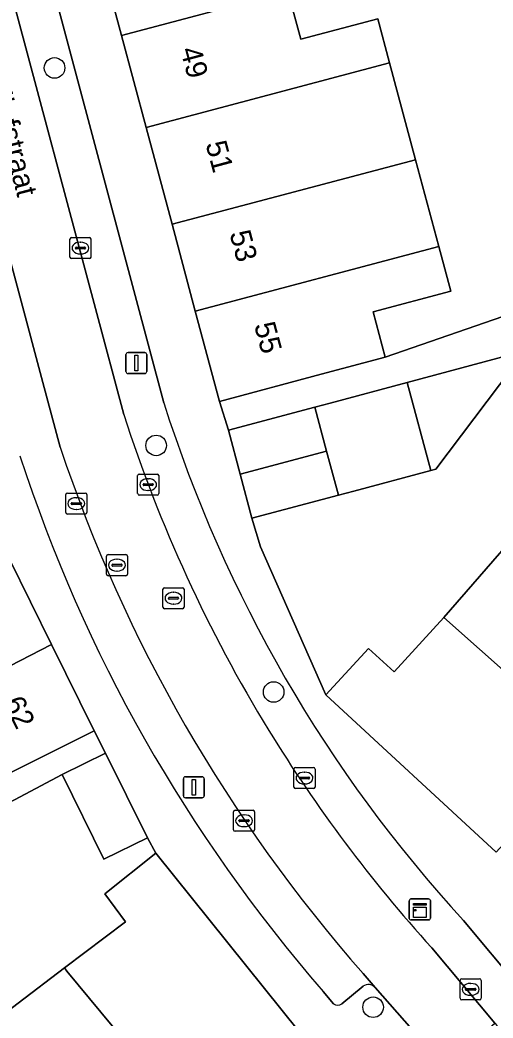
# Model space of a CAD drawing. Extents: x 162542 to 163147, y 380779 to 381521.
# Drawn here: x 163005.41 to 163027.86, y 380934.95 to 380982.36 of the extents above; entities that cross this region are included whole.
import ezdxf

# ---------------------------------------------------------------- set-up
doc = ezdxf.new("R2010")
doc.units = 0
for name, color, linetype in [('IMGEO_Boom', 7, 'Continuous'), ('IMGEO_Erf', 7, 'Continuous'), ('IMGEO_Kast', 7, 'Continuous'), ('IMGEO_Kolk', 7, 'Continuous'), ('IMGEO_Lichtmast', 7, 'Continuous'), ('IMGEO_Muur', 7, 'Continuous'), ('IMGEO_Openbare_ruimte_label', 7, 'Continuous'), ('IMGEO_Pand', 7, 'Continuous'), ('IMGEO_Pand_nummerreeks', 7, 'Continuous'), ('IMGEO_Parkeervlak_open', 7, 'Continuous'), ('IMGEO_Rijbaan_lokaal_open', 7, 'Continuous'), ('IMGEO_Rioolput', 7, 'Continuous'), ('IMGEO_Voetpad_open', 7, 'Continuous')]:
    doc.layers.add(name, color=color, linetype=linetype)

msp = doc.modelspace()

# ---------------------------------------------------------------- linework, layer by layer
at = {"layer": 'IMGEO_Boom'}
for centre in [(163007.052, 380980.083), (163011.873, 380962.151), (163017.451, 380950.44), (163022.172, 380935.467)]:
    msp.add_circle(centre, 0.489, dxfattribs=at)
at = {"layer": 'IMGEO_Erf'}
for points in [[(163018.128, 380983.725), (163018.739, 380981.442), (163022.394, 380982.42), (163022.954, 380980.325), (163024.185, 380975.725), (163025.287, 380971.603), (163025.853, 380969.486), (163022.173, 380968.502), (163022.75, 380966.347), (163029.615, 380968.727)], [(163029.387, 380966.638), (163025.146, 380961.029), (163024.914, 380960.967), (163021.252, 380959.987), (163020.522, 380959.792), (163016.421, 380958.694), (163016.826, 380957.343), (163019.935, 380950.306), (163021.945, 380952.504), (163023.178, 380951.397), (163025.524, 380953.976), (163028.918, 380957.88)], [(163003.112, 380933.989), (163007.525, 380937.333), (163010.415, 380939.523), (163009.443, 380940.848), (163011.851, 380942.784), (163011.456, 380943.508), (163009.388, 380942.492), (163007.409, 380946.521), (163003.382, 380944.389), (163004.906, 380941.323), (163000.218, 380938.994), (162999.703, 380940.03), (162998.96, 380939.661), (162995.276, 380937.727), (162992.073, 380936.046), (162991.882, 380935.769), (162989.247, 380931.936)]]:
    msp.add_lwpolyline(points, dxfattribs=at)
at = {"layer": 'IMGEO_Kast'}
for p, q in [((163023.89, 380939.686), (163023.89, 380940.527)), ((163023.89, 380940.527), (163023.89, 380939.686)), ((163023.965, 380940.611), (163024.806, 380940.611)), ((163024.806, 380940.611), (163023.965, 380940.611)), ((163024.89, 380940.536), (163024.89, 380939.695)), ((163024.89, 380939.695), (163024.89, 380940.536)), ((163024.815, 380939.611), (163023.974, 380939.611)), ((163023.974, 380939.611), (163024.815, 380939.611))]:
    msp.add_line(p, q, dxfattribs=at)
for points in [[(163024.085, 380940.401), (163024.685, 380940.401), (163024.685, 380940.316), (163024.085, 380940.316), (163024.085, 380940.401)], [(163024.085, 380940.226), (163024.685, 380940.226), (163024.685, 380939.737), (163024.085, 380939.737), (163024.085, 380940.226)]]:
    msp.add_lwpolyline(points, dxfattribs=at)
msp.add_circle((163024.169, 380940.075), 0.0377, dxfattribs=at)
for centre, start, end in [((163023.968, 380940.533), 92.4484, 184.2845), ((163023.968, 380940.533), 92.4484, 184.2845), ((163024.812, 380940.533), 2.4484, 94.2845), ((163024.812, 380940.533), 2.4484, 94.2845), ((163023.968, 380939.689), 182.4484, 274.2845), ((163023.968, 380939.689), 182.4484, 274.2845), ((163024.812, 380939.689), 272.4484, 4.2845), ((163024.812, 380939.689), 272.4484, 4.2845)]:
    msp.add_arc(centre, 0.0779, start, end, dxfattribs=at)
at = {"layer": 'IMGEO_Kolk'}
for p, q in [((163007.78, 380971.1), (163007.78, 380971.952)), ((163007.855, 380972.026), (163008.707, 380972.026)), ((163008.268, 380971.806), (163008.293, 380971.806)), ((163008.781, 380971.952), (163008.781, 380971.1)), ((163008.039, 380971.52), (163008.039, 380971.532)), ((163008.477, 380971.483), (163008.079, 380971.483)), ((163008.082, 380971.569), (163008.48, 380971.569)), ((163008.291, 380971.246), (163008.266, 380971.246)), ((163008.523, 380971.532), (163008.523, 380971.52)), ((163008.707, 380971.026), (163007.855, 380971.026)), ((163011.071, 380960.791), (163011.923, 380960.791)), ((163010.996, 380959.865), (163010.996, 380960.717)), ((163011.255, 380960.285), (163011.255, 380960.297)), ((163011.298, 380960.334), (163011.696, 380960.334)), ((163011.484, 380960.571), (163011.509, 380960.571)), ((163011.739, 380960.297), (163011.739, 380960.285)), ((163011.997, 380960.717), (163011.997, 380959.865)), ((163007.584, 380958.964), (163007.584, 380959.816)), ((163007.659, 380959.89), (163008.511, 380959.89)), ((163008.585, 380959.816), (163008.585, 380958.964)), ((163011.923, 380959.791), (163011.071, 380959.791)), ((163011.693, 380960.248), (163011.295, 380960.248)), ((163011.507, 380960.011), (163011.482, 380960.011)), ((163007.843, 380959.384), (163007.843, 380959.396)), ((163008.281, 380959.347), (163007.883, 380959.347)), ((163007.886, 380959.433), (163008.284, 380959.433)), ((163008.072, 380959.67), (163008.097, 380959.67)), ((163008.327, 380959.396), (163008.327, 380959.384)), ((163008.511, 380958.89), (163007.659, 380958.89)), ((163008.095, 380959.11), (163008.07, 380959.11)), ((163018.414, 380945.927), (163018.414, 380946.779)), ((163018.489, 380946.853), (163019.341, 380946.853)), ((163018.902, 380946.633), (163018.927, 380946.633)), ((163019.415, 380946.779), (163019.415, 380945.927)), ((163018.673, 380946.347), (163018.673, 380946.359)), ((163019.111, 380946.31), (163018.713, 380946.31)), ((163018.716, 380946.396), (163019.114, 380946.396)), ((163018.925, 380946.073), (163018.9, 380946.073)), ((163019.157, 380946.359), (163019.157, 380946.347)), ((163019.341, 380945.853), (163018.489, 380945.853)), ((163015.545, 380943.899), (163015.545, 380944.751)), ((163015.62, 380944.825), (163016.472, 380944.825)), ((163016.546, 380944.751), (163016.546, 380943.899)), ((163015.804, 380944.319), (163015.804, 380944.331)), ((163016.242, 380944.282), (163015.844, 380944.282)), ((163015.847, 380944.368), (163016.245, 380944.368)), ((163016.033, 380944.605), (163016.058, 380944.605)), ((163016.288, 380944.331), (163016.288, 380944.319)), ((163016.472, 380943.825), (163015.62, 380943.825)), ((163016.056, 380944.045), (163016.031, 380944.045)), ((163026.302, 380935.89), (163026.302, 380936.742)), ((163026.377, 380936.816), (163027.229, 380936.816)), ((163026.79, 380936.596), (163026.815, 380936.596)), ((163027.303, 380936.742), (163027.303, 380935.89)), ((163026.561, 380936.31), (163026.561, 380936.322)), ((163026.999, 380936.273), (163026.601, 380936.273)), ((163026.604, 380936.359), (163027.002, 380936.359)), ((163027.045, 380936.322), (163027.045, 380936.31)), ((163027.229, 380935.816), (163026.377, 380935.816)), ((163026.813, 380936.036), (163026.788, 380936.036))]:
    msp.add_line(p, q, dxfattribs=at)
for points in [[(163007.78, 380971.1), (163007.78, 380971.952)], [(163007.855, 380972.026), (163008.707, 380972.026)], [(163008.781, 380971.952), (163008.781, 380971.1)], [(163008.707, 380971.026), (163007.855, 380971.026)], [(163011.071, 380960.791), (163011.923, 380960.791)], [(163010.996, 380959.865), (163010.996, 380960.717)], [(163011.997, 380960.717), (163011.997, 380959.865)], [(163007.584, 380958.964), (163007.584, 380959.816)], [(163007.659, 380959.89), (163008.511, 380959.89)], [(163008.585, 380959.816), (163008.585, 380958.964)], [(163011.923, 380959.791), (163011.071, 380959.791)], [(163008.511, 380958.89), (163007.659, 380958.89)], [(163018.414, 380945.927), (163018.414, 380946.779)], [(163018.489, 380946.853), (163019.341, 380946.853)], [(163019.415, 380946.779), (163019.415, 380945.927)], [(163019.341, 380945.853), (163018.489, 380945.853)], [(163015.545, 380943.899), (163015.545, 380944.751)], [(163015.62, 380944.825), (163016.472, 380944.825)], [(163016.546, 380944.751), (163016.546, 380943.899)], [(163016.472, 380943.825), (163015.62, 380943.825)], [(163026.302, 380935.89), (163026.302, 380936.742)], [(163026.377, 380936.816), (163027.229, 380936.816)], [(163027.303, 380936.742), (163027.303, 380935.89)], [(163027.229, 380935.816), (163026.377, 380935.816)]]:
    msp.add_lwpolyline(points, dxfattribs=at)
for centre, radius, start, end in [((163007.857, 380971.95), 0.0765, 91.552, 178.448), ((163007.857, 380971.95), 0.0765, 91.552, 178.448), ((163008.705, 380971.95), 0.0765, 1.552, 88.448), ((163008.705, 380971.95), 0.0765, 1.552, 88.448), ((163008.079, 380971.529), 0.0403, 85.8775, 175.7526), ((163008.076, 380971.519), 0.0366, 178.938, 274.7102), ((163008.48, 380971.526), 0.043, 264.8664, 352.4533), ((163008.484, 380971.531), 0.0386, 1.7309, 96.639), ((163007.857, 380971.102), 0.0765, 181.552, 268.448), ((163007.857, 380971.102), 0.0765, 181.552, 268.448), ((163008.705, 380971.102), 0.0765, 271.552, 358.448), ((163008.705, 380971.102), 0.0765, 271.552, 358.448), ((163011.073, 380960.715), 0.0765, 91.552, 178.448), ((163011.073, 380960.715), 0.0765, 91.552, 178.448), ((163011.921, 380960.715), 0.0765, 1.552, 88.448), ((163011.921, 380960.715), 0.0765, 1.552, 88.448), ((163011.295, 380960.294), 0.0403, 85.8775, 175.7526), ((163011.292, 380960.284), 0.0366, 178.938, 274.7102), ((163011.696, 380960.291), 0.043, 264.8664, 352.4533), ((163011.7, 380960.296), 0.0386, 1.7309, 96.639), ((163007.661, 380959.814), 0.0765, 91.552, 178.448), ((163007.661, 380959.814), 0.0765, 91.552, 178.448), ((163008.509, 380959.814), 0.0765, 1.552, 88.448), ((163008.509, 380959.814), 0.0765, 1.552, 88.448), ((163011.073, 380959.867), 0.0765, 181.552, 268.448), ((163011.073, 380959.867), 0.0765, 181.552, 268.448), ((163011.921, 380959.867), 0.0765, 271.552, 358.448), ((163011.921, 380959.867), 0.0765, 271.552, 358.448), ((163007.883, 380959.393), 0.0403, 85.8775, 175.7526), ((163007.88, 380959.383), 0.0366, 178.938, 274.7102), ((163008.284, 380959.39), 0.043, 264.8664, 352.4533), ((163008.288, 380959.395), 0.0386, 1.7309, 96.639), ((163007.661, 380958.966), 0.0765, 181.552, 268.448), ((163007.661, 380958.966), 0.0765, 181.552, 268.448), ((163008.509, 380958.966), 0.0765, 271.552, 358.448), ((163008.509, 380958.966), 0.0765, 271.552, 358.448), ((163018.491, 380946.777), 0.0765, 91.552, 178.448), ((163018.491, 380946.777), 0.0765, 91.552, 178.448), ((163019.339, 380946.777), 0.0765, 1.552, 88.448), ((163019.339, 380946.777), 0.0765, 1.552, 88.448), ((163018.713, 380946.356), 0.0403, 85.8775, 175.7526), ((163018.71, 380946.346), 0.0366, 178.938, 274.7102), ((163019.114, 380946.353), 0.043, 264.8664, 352.4533), ((163019.118, 380946.358), 0.0386, 1.7309, 96.639), ((163018.491, 380945.929), 0.0765, 181.552, 268.448), ((163018.491, 380945.929), 0.0765, 181.552, 268.448), ((163019.339, 380945.929), 0.0765, 271.552, 358.448), ((163019.339, 380945.929), 0.0765, 271.552, 358.448), ((163015.622, 380944.749), 0.0765, 91.552, 178.448), ((163015.622, 380944.749), 0.0765, 91.552, 178.448), ((163016.47, 380944.749), 0.0765, 1.552, 88.448), ((163016.47, 380944.749), 0.0765, 1.552, 88.448), ((163015.844, 380944.328), 0.0403, 85.8775, 175.7526), ((163015.841, 380944.318), 0.0366, 178.938, 274.7102), ((163016.245, 380944.325), 0.043, 264.8664, 352.4533), ((163016.249, 380944.33), 0.0386, 1.7309, 96.639), ((163015.622, 380943.901), 0.0765, 181.552, 268.448), ((163015.622, 380943.901), 0.0765, 181.552, 268.448), ((163016.47, 380943.901), 0.0765, 271.552, 358.448), ((163016.47, 380943.901), 0.0765, 271.552, 358.448), ((163026.379, 380936.74), 0.0765, 91.552, 178.448), ((163026.379, 380936.74), 0.0765, 91.552, 178.448), ((163027.227, 380936.74), 0.0765, 1.552, 88.448), ((163027.227, 380936.74), 0.0765, 1.552, 88.448), ((163026.601, 380936.319), 0.0403, 85.8775, 175.7526), ((163026.598, 380936.309), 0.0366, 178.938, 274.7102), ((163027.002, 380936.316), 0.043, 264.8664, 352.4533), ((163027.006, 380936.321), 0.0386, 1.7309, 96.639), ((163026.379, 380935.892), 0.0765, 181.552, 268.448), ((163026.379, 380935.892), 0.0765, 181.552, 268.448), ((163027.227, 380935.892), 0.0765, 271.552, 358.448), ((163027.227, 380935.892), 0.0765, 271.552, 358.448)]:
    msp.add_arc(centre, radius, start, end, dxfattribs=at)
for centre, major_axis, ratio, start_param, end_param in [((163008.267, 380971.526), (-0.387, 0.002), 0.722429, 4.712389, 7.853982), ((163008.292, 380971.526), (-0.39, 0.002), 0.717154, 1.570796, 4.712389), ((163011.483, 380960.291), (-0.387, 0.002), 0.722429, 4.712389, 7.853982), ((163011.508, 380960.291), (-0.39, 0.002), 0.717154, 1.570796, 4.712389), ((163008.071, 380959.39), (-0.387, 0.002), 0.722429, 4.712389, 7.853982), ((163008.096, 380959.39), (-0.39, 0.002), 0.717154, 1.570796, 4.712389), ((163018.901, 380946.353), (-0.387, 0.002), 0.722429, 4.712389, 7.853982), ((163018.926, 380946.353), (-0.39, 0.002), 0.717154, 1.570796, 4.712389), ((163016.032, 380944.325), (-0.387, 0.002), 0.722429, 4.712389, 7.853982), ((163016.057, 380944.325), (-0.39, 0.002), 0.717154, 1.570796, 4.712389), ((163026.789, 380936.316), (-0.387, 0.002), 0.722429, 4.712389, 7.853982), ((163026.814, 380936.316), (-0.39, 0.002), 0.717154, 1.570796, 4.712389)]:
    msp.add_ellipse(centre, major_axis=major_axis, ratio=ratio, start_param=start_param, end_param=end_param, dxfattribs=at)
at = {"layer": 'IMGEO_Lichtmast'}
for p, q in [((163010.439, 380965.665), (163010.439, 380966.465)), ((163010.439, 380966.465), (163010.439, 380965.665)), ((163010.539, 380966.565), (163011.329, 380966.565)), ((163011.329, 380966.565), (163010.539, 380966.565)), ((163011.429, 380966.465), (163011.429, 380965.665)), ((163011.429, 380965.665), (163011.429, 380966.465)), ((163011.329, 380965.565), (163010.539, 380965.565)), ((163010.539, 380965.565), (163011.329, 380965.565)), ((163013.164, 380945.516), (163013.164, 380946.316)), ((163013.164, 380946.316), (163013.164, 380945.516)), ((163013.264, 380946.416), (163014.054, 380946.416)), ((163014.054, 380946.416), (163013.264, 380946.416)), ((163014.154, 380946.316), (163014.154, 380945.516)), ((163014.154, 380945.516), (163014.154, 380946.316)), ((163014.054, 380945.416), (163013.264, 380945.416)), ((163013.264, 380945.416), (163014.054, 380945.416))]:
    msp.add_line(p, q, dxfattribs=at)
for points in [[(163010.859, 380966.44), (163011.009, 380966.44), (163011.009, 380965.69), (163010.859, 380965.69), (163010.859, 380966.44)], [(163013.584, 380946.291), (163013.734, 380946.291), (163013.734, 380945.541), (163013.584, 380945.541), (163013.584, 380946.291)]]:
    msp.add_lwpolyline(points, dxfattribs=at)
for centre, start, end in [((163010.539, 380966.465), 90, 180), ((163010.539, 380966.465), 90, 180), ((163011.329, 380966.465), 0, 90), ((163011.329, 380966.465), 360, 90), ((163010.539, 380965.665), 180, 270), ((163010.539, 380965.665), 180, 270), ((163011.329, 380965.665), 270, 0), ((163011.329, 380965.665), 270, 0), ((163013.264, 380946.316), 90, 180), ((163013.264, 380946.316), 90, 180), ((163014.054, 380946.316), 0, 90), ((163014.054, 380946.316), 360, 90), ((163013.264, 380945.516), 180, 270), ((163013.264, 380945.516), 180, 270), ((163014.054, 380945.516), 270, 0), ((163014.054, 380945.516), 270, 0)]:
    msp.add_arc(centre, 0.1, start, end, dxfattribs=at)
at = {"layer": 'IMGEO_Muur'}
msp.add_lwpolyline([(163019.935, 380950.306), (163016.826, 380957.343), (163016.421, 380958.694)], dxfattribs=at)
at = {"layer": 'IMGEO_Pand'}
for points in [[(163010.224, 380981.627), (163018.128, 380983.725), (163017.535, 380985.943), (163021.103, 380986.898), (163020.535, 380989.047), (163009.053, 380985.998)], [(163010.224, 380981.627), (163011.395, 380977.257), (163022.954, 380980.325), (163022.394, 380982.42), (163018.739, 380981.442), (163018.128, 380983.725)], [(163012.627, 380972.658), (163024.185, 380975.725), (163022.954, 380980.325), (163011.395, 380977.257)], [(163013.731, 380968.537), (163025.287, 380971.603), (163024.185, 380975.725), (163012.627, 380972.658)], [(163013.731, 380968.537), (163014.882, 380964.241), (163019.712, 380965.534), (163022.75, 380966.347), (163022.173, 380968.502), (163025.853, 380969.486), (163025.287, 380971.603)], [(163024.914, 380960.967), (163025.146, 380961.029), (163029.387, 380966.638), (163023.794, 380965.142)], [(163019.402, 380963.967), (163019.962, 380961.879), (163020.522, 380959.792), (163021.252, 380959.987), (163024.914, 380960.967), (163023.794, 380965.142), (163020.135, 380964.163)], [(163015.863, 380960.782), (163019.962, 380961.879), (163019.402, 380963.967), (163015.304, 380962.87)], [(163015.863, 380960.782), (163016.421, 380958.694), (163020.522, 380959.792), (163019.962, 380961.879)], [(163028.918, 380957.88), (163025.524, 380953.976), (163033.706, 380946.704), (163035.252, 380948.428), (163035.789, 380947.935), (163037.619, 380950.114), (163037.102, 380950.637), (163037.57, 380951.213)], [(163006.91, 380952.69), (163004.915, 380956.745), (163000, 380955.425), (162993.392, 380953.65), (162993.924, 380951.587), (162995.502, 380947.7), (162996.171, 380947.908), (162999.831, 380949.044), (163000, 380949.131)], [(163025.524, 380953.976), (163023.178, 380951.397), (163021.945, 380952.504), (163019.935, 380950.306), (163028.009, 380942.84), (163029.375, 380944.322), (163031.075, 380942.682), (163031.789, 380943.488), (163032.484, 380942.824), (163034.394, 380944.993), (163033.728, 380945.606), (163034.243, 380946.227), (163033.706, 380946.704)], [(162996.171, 380947.908), (162997.328, 380945.556), (162998.411, 380943.355), (163000, 380944.136), (163004.454, 380946.36), (163008.927, 380948.593), (163006.91, 380952.69), (163000, 380949.131), (162999.831, 380949.044)], [(163009.477, 380947.537), (163007.409, 380946.521), (163009.388, 380942.492), (163011.456, 380943.508)], [(163007.525, 380937.333), (163007.628, 380937.177), (163014.547, 380928.837), (163015.102, 380928.325), (163015.784, 380928.911), (163016.3, 380928.348), (163018.558, 380930.096), (163018.122, 380930.758), (163018.745, 380931.225), (163017.275, 380933.033), (163018.7, 380934.274), (163011.851, 380942.784), (163009.443, 380940.848), (163010.415, 380939.523)], [(163007.525, 380937.333), (163003.112, 380933.989), (163003.23, 380933.813), (163009.873, 380925.072), (163010.56, 380925.593), (163011.078, 380924.98), (163013.305, 380926.766), (163012.859, 380927.379), (163014.547, 380928.837), (163007.628, 380937.177)]]:
    msp.add_lwpolyline(points, close=True, dxfattribs=at)
at = {"layer": 'IMGEO_Parkeervlak_open'}
for points in [[(162977.093, 381087.926), (162983.381, 381064.467), (162989.209, 381042.691), (162990.072, 381039.464), (162991.279, 381034.955), (162999.787, 381003.044), (163003.342, 380989.772), (163004.203, 380986.558), (163006.3, 380978.73), (163010.339, 380963.624)], [(163012.239, 380964.181), (163008.155, 380979.475), (163001.717, 381003.588), (162993.168, 381035.439), (162985.284, 381065.06), (162979.22, 381087.75)], [(163007.316, 380962.07), (163006.499, 380965.138), (163001.013, 380985.655), (163000.14, 380988.922), (162999.993, 380989.471), (162993.511, 381013.755), (162989.412, 381029.037), (162986.861, 381038.573), (162986, 381041.79), (162982.725, 381054.03), (162974.643, 381084.361)], [(163029.107, 380936.42), (163026.468, 380939.582)], [(163024.952, 380938.294), (163027.953, 380934.71), (163028.062, 380934.579)], [(163022.272, 380936.401), (163021.701, 380937.068)], [(163019.801, 380936.217), (163020.293, 380935.634)], [(163020.682, 380935.627), (163021.692, 380936.468)]]:
    msp.add_lwpolyline(points, dxfattribs=at)
for centre, radius, start, end in [((163074.785, 380983.945), 65.595, 197.53631, 222.55714), ((163076.19, 380984.744), 69.155, 197.78202, 211.50032), ((163076.376, 380985.165), 72.819, 198.49067, 221.33761), ((163075.12, 380984.303), 73.297, 197.99917, 220.99892), ((163076.22, 380984.741), 69.179, 211.48579, 222.17576), ((163021.941, 380936.082), 0.46, 43.9758, 122.8453), ((163020.492, 380935.885), 0.321, 231.6031, 306.3351)]:
    msp.add_arc(centre, radius, start, end, dxfattribs=at)
at = {"layer": 'IMGEO_Rijbaan_lokaal_open'}
for points in [[(163006.3, 380978.73), (163004.203, 380986.558), (163001.013, 380985.655), (163006.499, 380965.138), (163007.316, 380962.07)], [(163010.339, 380963.624), (163006.3, 380978.73)], [(163021.701, 380937.068), (163022.272, 380936.401), (163024.01, 380934.429), (163025.483, 380932.592), (163027.953, 380934.71), (163024.952, 380938.294)]]:
    msp.add_lwpolyline(points, dxfattribs=at)
for centre, radius, start, end in [((163076.19, 380984.744), 69.155, 197.78202, 211.50032), ((163076.376, 380985.165), 72.819, 198.49067, 221.33761), ((163076.22, 380984.741), 69.179, 211.48579, 222.17576)]:
    msp.add_arc(centre, radius, start, end, dxfattribs=at)
at = {"layer": 'IMGEO_Rioolput'}
for p, q in [((163009.589, 380956.965), (163010.441, 380956.965)), ((163009.514, 380956.039), (163009.514, 380956.891)), ((163009.773, 380956.459), (163009.773, 380956.471)), ((163009.816, 380956.508), (163010.214, 380956.508)), ((163010.002, 380956.745), (163010.027, 380956.745)), ((163010.257, 380956.471), (163010.257, 380956.459)), ((163010.515, 380956.891), (163010.515, 380956.039)), ((163010.211, 380956.422), (163009.813, 380956.422)), ((163010.025, 380956.185), (163010, 380956.185)), ((163010.441, 380955.965), (163009.589, 380955.965)), ((163012.196, 380954.469), (163012.196, 380955.321)), ((163012.271, 380955.395), (163013.123, 380955.395)), ((163012.684, 380955.175), (163012.709, 380955.175)), ((163013.197, 380955.321), (163013.197, 380954.469)), ((163012.455, 380954.889), (163012.455, 380954.901)), ((163012.893, 380954.852), (163012.495, 380954.852)), ((163012.498, 380954.938), (163012.896, 380954.938)), ((163012.707, 380954.615), (163012.682, 380954.615)), ((163012.939, 380954.901), (163012.939, 380954.889)), ((163013.123, 380954.395), (163012.271, 380954.395))]:
    msp.add_line(p, q, dxfattribs=at)
for points in [[(163009.589, 380956.965), (163010.441, 380956.965)], [(163009.514, 380956.039), (163009.514, 380956.891)], [(163010.515, 380956.891), (163010.515, 380956.039)], [(163010.441, 380955.965), (163009.589, 380955.965)], [(163012.196, 380954.469), (163012.196, 380955.321)], [(163012.271, 380955.395), (163013.123, 380955.395)], [(163013.197, 380955.321), (163013.197, 380954.469)], [(163013.123, 380954.395), (163012.271, 380954.395)]]:
    msp.add_lwpolyline(points, dxfattribs=at)
for centre, radius, start, end in [((163009.591, 380956.889), 0.0765, 91.552, 178.448), ((163009.591, 380956.889), 0.0765, 91.552, 178.448), ((163010.439, 380956.889), 0.0765, 1.552, 88.448), ((163010.439, 380956.889), 0.0765, 1.552, 88.448), ((163009.813, 380956.468), 0.0403, 85.8775, 175.7526), ((163010.218, 380956.47), 0.0386, 1.7309, 96.639), ((163009.591, 380956.041), 0.0765, 181.552, 268.448), ((163009.591, 380956.041), 0.0765, 181.552, 268.448), ((163009.81, 380956.458), 0.0366, 178.938, 274.7102), ((163010.214, 380956.465), 0.043, 264.8664, 352.4533), ((163010.439, 380956.041), 0.0765, 271.552, 358.448), ((163010.439, 380956.041), 0.0765, 271.552, 358.448), ((163012.273, 380955.319), 0.0765, 91.552, 178.448), ((163012.273, 380955.319), 0.0765, 91.552, 178.448), ((163013.121, 380955.319), 0.0765, 1.552, 88.448), ((163013.121, 380955.319), 0.0765, 1.552, 88.448), ((163012.495, 380954.898), 0.0403, 85.8775, 175.7526), ((163012.492, 380954.888), 0.0366, 178.938, 274.7102), ((163012.896, 380954.895), 0.043, 264.8664, 352.4533), ((163012.9, 380954.9), 0.0386, 1.7309, 96.639), ((163012.273, 380954.471), 0.0765, 181.552, 268.448), ((163012.273, 380954.471), 0.0765, 181.552, 268.448), ((163013.121, 380954.471), 0.0765, 271.552, 358.448), ((163013.121, 380954.471), 0.0765, 271.552, 358.448)]:
    msp.add_arc(centre, radius, start, end, dxfattribs=at)
for centre, major_axis, ratio, start_param, end_param in [((163010.001, 380956.465), (-0.387, 0.002), 0.722429, 4.712389, 7.853982), ((163010.026, 380956.465), (-0.39, 0.002), 0.717154, 1.570796, 4.712389), ((163012.683, 380954.895), (-0.387, 0.002), 0.722429, 4.712389, 7.853982), ((163012.708, 380954.895), (-0.39, 0.002), 0.717154, 1.570796, 4.712389)]:
    msp.add_ellipse(centre, major_axis=major_axis, ratio=ratio, start_param=start_param, end_param=end_param, dxfattribs=at)
at = {"layer": 'IMGEO_Voetpad_open'}
for points in [[(162979.22, 381087.75), (162985.284, 381065.06), (162993.168, 381035.439), (163001.717, 381003.588), (163008.155, 380979.475), (163012.239, 380964.181)], [(163028.009, 380942.84), (163019.935, 380950.306), (163016.826, 380957.343), (163016.421, 380958.694), (163015.863, 380960.782), (163015.304, 380962.87), (163014.882, 380964.241), (163013.731, 380968.537), (163012.627, 380972.658), (163011.395, 380977.257), (163010.224, 380981.627), (163009.053, 380985.998)], [(162998.142, 380982.951), (162999.27, 380978.582), (163000, 380975.752), (163000.397, 380974.215), (163001.524, 380969.847), (163002.651, 380965.479), (163003.778, 380961.11), (163004.915, 380956.745), (163006.91, 380952.69), (163008.927, 380948.593), (163009.477, 380947.537), (163011.456, 380943.508), (163011.851, 380942.784), (163018.7, 380934.274), (163020.715, 380931.793), (163024.01, 380934.429)], [(163029.615, 380968.727), (163022.75, 380966.347), (163019.712, 380965.534), (163014.882, 380964.241), (163015.304, 380962.87), (163019.402, 380963.967), (163020.135, 380964.163), (163023.794, 380965.142), (163029.387, 380966.638)], [(163003.382, 380944.389), (163007.409, 380946.521), (163009.477, 380947.537), (163008.927, 380948.593), (163004.454, 380946.36)], [(163026.468, 380939.582), (163029.107, 380936.42), (163032.712, 380939.901)], [(163020.293, 380935.634), (163019.801, 380936.217)], [(163021.692, 380936.468), (163020.682, 380935.627)], [(163024.01, 380934.429), (163022.272, 380936.401)]]:
    msp.add_lwpolyline(points, dxfattribs=at)
for centre, radius, start, end in [((163074.785, 380983.945), 65.595, 197.53631, 222.55714), ((163075.12, 380984.303), 73.297, 197.99917, 220.99892), ((163021.941, 380936.082), 0.46, 43.9758, 122.8453), ((163020.492, 380935.885), 0.321, 231.6031, 306.3351)]:
    msp.add_arc(centre, radius, start, end, dxfattribs=at)

# ---------------------------------------------------------------- texts
at = {"layer": 'IMGEO_Openbare_ruimte_label'}
msp.add_text('Madeliefstraat', height=1, rotation=284.6619, dxfattribs=at).set_placement((163003.169, 380982.026))
at = {"layer": 'IMGEO_Pand_nummerreeks'}
for s, rotation, p in [('49', 284.9998, (163013.015, 380980.947)), ('51', 284.9998, (163014.211, 380976.479)), ('53', 284.9998, (163015.35, 380972.23)), ('55', 284.9998, (163016.518, 380967.871)), ('62', 296.2115, (163004.61, 380949.937))]:
    msp.add_text(s, height=1, rotation=rotation, dxfattribs=at).set_placement(p)

doc.saveas('drawing.dxf')
